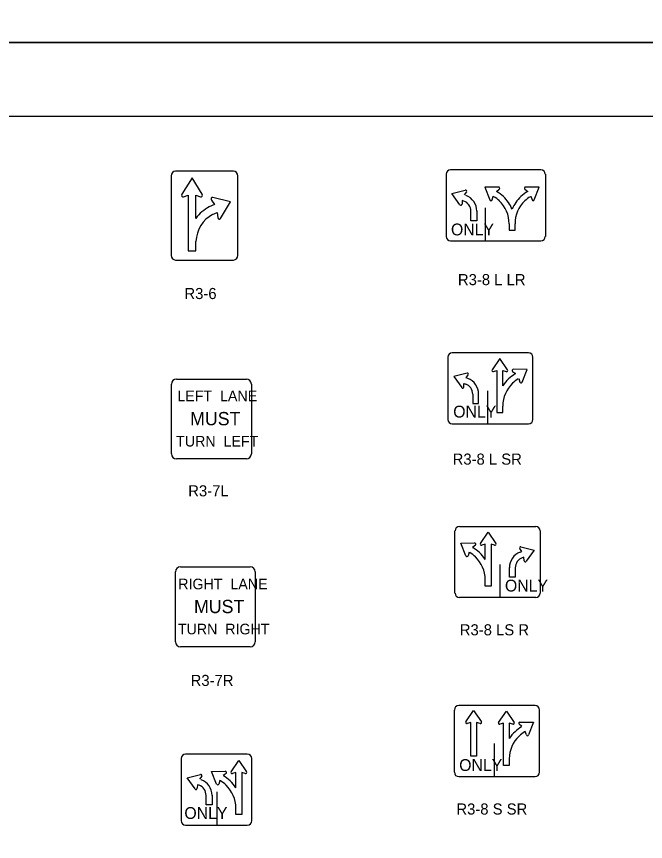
# Model space of a CAD drawing. Extents: x 42133 to 45533, y 41351 to 47951.
# Drawn here: x 42559 to 42984, y 43012 to 43569 of the extents above; entities that cross this region are included whole.
import ezdxf

# ---------------------------------------------------------------- set-up
doc = ezdxf.new("R2010")
doc.units = 0
for name, color, linetype in [('#plot_shape', 7, 'Continuous'), ('P_ODOT_PLAN_Border', 7, 'Continuous'), ('P_TRAF_SIGN_SignDetails', 7, 'Continuous')]:
    doc.layers.add(name, color=color, linetype=linetype)

msp = doc.modelspace()

# ---------------------------------------------------------------- linework, layer by layer
at = {"layer": '#plot_shape'}
for points in [[(42133.34, 43551.35), (43833.34, 43551.35), (43833.34, 44651.35), (42133.34, 44651.35)], [(42133.34, 42451.35), (43833.34, 42451.35), (43833.34, 43551.35), (42133.34, 43551.35)]]:
    msp.add_lwpolyline(points, close=True, dxfattribs=at)
at = {"layer": 'P_ODOT_PLAN_Border'}
msp.add_lwpolyline([(42208.34, 42501.35), (43808.34, 42501.35), (43808.34, 43501.35), (42208.34, 43501.35)], close=True, dxfattribs=at)
at = {"layer": 'P_TRAF_SIGN_SignDetails'}
for p, q in [((42663.19, 43461.28), (42663.19, 43407.53)), ((42699.13, 43464.4), (42666, 43464.4)), ((42705.35, 43464.4), (42699.13, 43464.4)), ((42708.17, 43454.37), (42708.17, 43461.28)), ((42849, 43462.36), (42849, 43420.39)), ((42913.14, 43465.35), (42851.99, 43465.35)), ((42916.13, 43462.36), (42916.13, 43420.39)), ((42677.27, 43460.03), (42670.44, 43448.8)), ((42684.11, 43448.8), (42677.27, 43460.03)), ((42708.17, 43407.53), (42708.17, 43454.37)), ((42853.01, 43449.36), (42861.98, 43451.63)), ((42862.8, 43450.38), (42861.28, 43448.43)), ((42884.52, 43453.73), (42875.27, 43453.68)), ((42875.27, 43453.68), (42878.64, 43445.07)), ((42883.08, 43450.77), (42885.01, 43452.34)), ((42902.26, 43452.34), (42904.2, 43450.77)), ((42912.01, 43453.68), (42902.76, 43453.73)), ((42908.64, 43445.07), (42912.01, 43453.68)), ((42671.59, 43447.09), (42674.63, 43448.16)), ((42674.63, 43448.16), (42674.63, 43410.67)), ((42679.88, 43432.46), (42679.88, 43448.17)), ((42679.88, 43448.17), (42682.95, 43447.09)), ((42690.36, 43444.77), (42692.4, 43442.03)), ((42703.28, 43443.76), (42691.36, 43446.61)), ((42858.36, 43441.81), (42853.01, 43449.36)), ((42859.92, 43444.69), (42859.79, 43442.22)), ((42861.1, 43444.25), (42859.92, 43444.69)), ((42880.12, 43445.13), (42880.85, 43447.49)), ((42880.85, 43447.49), (42881.28, 43447.2)), ((42906, 43447.2), (42906.42, 43447.49)), ((42906.42, 43447.49), (42907.15, 43445.13)), ((42692.4, 43442.03), (42688.94, 43440.36)), ((42696.49, 43432.51), (42703.28, 43443.76)), ((42875.52, 43439.76), (42875.52, 43417.48)), ((42691.13, 43435.07), (42694.37, 43436.63)), ((42694.37, 43436.63), (42694.62, 43433.07)), ((42865.8, 43431), (42865.8, 43437.48)), ((42869.79, 43437.64), (42869.79, 43431)), ((42869.79, 43431), (42865.8, 43431)), ((42891.64, 43428.93), (42891.64, 43424.53)), ((42895.63, 43424.53), (42895.63, 43428.93)), ((42891.64, 43424.53), (42895.63, 43424.53)), ((42891.64, 43424.53), (42895.63, 43424.53)), ((42679.88, 43410.67), (42679.88, 43416.98)), ((42851.99, 43417.4), (42913.14, 43417.4)), ((42674.63, 43410.67), (42679.88, 43410.67)), ((42666, 43404.42), (42705.35, 43404.42)), ((42850.21, 43338.76), (42850.21, 43296.77)), ((42904.79, 43341.76), (42853.2, 43341.76)), ((42907.78, 43296.77), (42907.78, 43338.76)), ((42885.38, 43337.96), (42880.15, 43330.32)), ((42890.62, 43330.32), (42885.38, 43337.96)), ((42863.2, 43328.02), (42854.23, 43325.76)), ((42881.03, 43329.13), (42883.39, 43329.86)), ((42883.39, 43329.86), (42883.39, 43301.38)), ((42887.38, 43319.45), (42887.38, 43329.86)), ((42887.38, 43329.86), (42889.74, 43329.13)), ((42894.01, 43329.2), (42895.94, 43327.65)), ((42903.77, 43330.55), (42894.51, 43330.61)), ((42895.94, 43327.65), (42895.61, 43327.43)), ((42900.4, 43321.93), (42903.77, 43330.55)), ((42666.79, 43324.02), (42714.02, 43324.02)), ((42854.23, 43325.76), (42859.58, 43318.21)), ((42862.5, 43324.83), (42864.02, 43326.78)), ((42863.7, 43324.39), (42862.5, 43324.83)), ((42898.18, 43324.35), (42898.91, 43321.99)), ((42663.42, 43273.42), (42663.42, 43320.65)), ((42717.39, 43320.65), (42717.39, 43273.42)), ((42861, 43318.61), (42861.14, 43321.08)), ((42861.14, 43321.08), (42862.32, 43320.64)), ((42877.22, 43293.8), (42877.22, 43316.14)), ((42867.02, 43313.87), (42867.02, 43307.39)), ((42871.01, 43307.39), (42871.01, 43314.03)), ((42867.02, 43307.39), (42871.01, 43307.39)), ((42887.38, 43301.38), (42887.38, 43305.78)), ((42883.39, 43301.38), (42887.38, 43301.38)), ((42853.2, 43293.78), (42904.79, 43293.78)), ((42714.02, 43270.05), (42666.79, 43270.05)), ((42855.05, 43179.44), (42855.05, 43221.44)), ((42858.05, 43224.43), (42909.64, 43224.43)), ((42912.63, 43221.44), (42912.63, 43179.44)), ((42872.21, 43213), (42877.45, 43220.64)), ((42877.45, 43220.64), (42882.68, 43213)), ((42859.06, 43213.22), (42868.32, 43213.28)), ((42862.44, 43204.61), (42859.06, 43213.22)), ((42868.82, 43211.88), (42866.9, 43210.32)), ((42866.9, 43210.32), (42867.22, 43210.1)), ((42875.46, 43212.53), (42873.1, 43211.8)), ((42875.46, 43202.13), (42875.46, 43212.53)), ((42881.8, 43211.8), (42879.45, 43212.53)), ((42879.45, 43212.53), (42879.45, 43184.05)), ((42899.63, 43210.7), (42908.61, 43208.44)), ((42864.66, 43207.02), (42863.93, 43204.66)), ((42900.34, 43207.5), (42898.82, 43209.46)), ((42899.13, 43207.06), (42900.34, 43207.5)), ((42908.61, 43208.44), (42903.26, 43200.88)), ((42901.7, 43203.75), (42900.52, 43203.32)), ((42901.84, 43201.29), (42901.7, 43203.75)), ((42666.04, 43146.53), (42666.04, 43193.75)), ((42669.4, 43197.13), (42716.63, 43197.13)), ((42720, 43193.75), (42720, 43146.53)), ((42885.62, 43176.47), (42885.62, 43198.81)), ((42891.83, 43190.06), (42891.83, 43196.71)), ((42895.82, 43196.55), (42895.82, 43190.06)), ((42875.46, 43184.05), (42875.46, 43188.45)), ((42895.82, 43190.06), (42891.83, 43190.06)), ((42879.45, 43184.05), (42875.46, 43184.05)), ((42909.64, 43176.45), (42858.05, 43176.45)), ((42716.63, 43143.16), (42669.4, 43143.16)), ((42854.6, 43100.4), (42854.6, 43058.41)), ((42909.19, 43103.39), (42857.59, 43103.39)), ((42862.41, 43092.49), (42867.65, 43100.12)), ((42867.65, 43100.12), (42872.88, 43092.49)), ((42884.55, 43091.96), (42889.78, 43099.59)), ((42889.78, 43099.59), (42895.02, 43091.96)), ((42912.18, 43058.41), (42912.18, 43100.4)), ((42865.65, 43092.03), (42863.29, 43091.29)), ((42865.65, 43069.31), (42865.65, 43092.03)), ((42872, 43091.29), (42869.64, 43092.03)), ((42869.64, 43092.03), (42869.64, 43069.31)), ((42887.79, 43091.49), (42885.43, 43090.77)), ((42887.79, 43063.01), (42887.79, 43091.49)), ((42894.14, 43090.77), (42891.78, 43091.49)), ((42891.78, 43091.49), (42891.78, 43081.09)), ((42900.33, 43089.29), (42898.41, 43090.84)), ((42898.91, 43092.23), (42908.17, 43092.19)), ((42908.17, 43092.19), (42904.79, 43083.57)), ((42902.57, 43085.99), (42902.15, 43085.69)), ((42903.3, 43083.63), (42902.57, 43085.99)), ((42881.57, 43077.79), (42881.57, 43055.5)), ((42669.98, 43067.67), (42669.98, 43025.67)), ((42714.58, 43070.66), (42672.98, 43070.66)), ((42703.65, 43058.76), (42708.89, 43066.4)), ((42708.89, 43066.4), (42714.12, 43058.76)), ((42717.64, 43025.67), (42717.64, 43067.67)), ((42869.64, 43069.31), (42865.65, 43069.31)), ((42891.78, 43067.42), (42891.78, 43063.01)), ((42891.78, 43063.01), (42887.79, 43063.01)), ((42674, 43054.66), (42682.97, 43056.93)), ((42679.35, 43047.11), (42674, 43054.66)), ((42683.79, 43055.69), (42682.28, 43053.73)), ((42690.5, 43058.99), (42699.76, 43059.04)), ((42693.88, 43050.37), (42690.5, 43058.99)), ((42700.26, 43057.64), (42698.34, 43056.09)), ((42706.89, 43058.3), (42704.54, 43057.57)), ((42706.89, 43047.89), (42706.89, 43058.3)), ((42713.25, 43057.57), (42710.89, 43058.3)), ((42710.89, 43058.3), (42710.89, 43029.81)), ((42857.59, 43055.41), (42909.19, 43055.41)), ((42680.91, 43049.99), (42680.78, 43047.52)), ((42682.09, 43049.55), (42680.91, 43049.99)), ((42696.1, 43052.79), (42695.36, 43050.43)), ((42696.52, 43052.49), (42696.1, 43052.79)), ((42694.09, 43045.06), (42694.09, 43022.77)), ((42686.79, 43036.29), (42686.79, 43042.78)), ((42690.78, 43042.94), (42690.78, 43036.29)), ((42690.78, 43036.29), (42686.79, 43036.29)), ((42706.89, 43029.81), (42706.89, 43034.22)), ((42710.89, 43029.81), (42706.89, 43029.81)), ((42672.98, 43022.68), (42714.65, 43022.68))]:
    msp.add_line(p, q, dxfattribs=at)
for centre, radius, start, end in [((42851.99, 43462.36), 2.99, 90, 180), ((42913.13, 43462.36), 2.99, 360, 90), ((42862.18, 43450.87), 0.785, 321.8979, 104.4235), ((42870.48, 43428.98), 25.16, 46.5584, 59.9731), ((42884.51, 43452.95), 0.788, 309.1769, 90.0726), ((42916.79, 43428.98), 25.16, 120.0268, 133.4416), ((42902.76, 43452.95), 0.788, 89.9274, 230.8231), ((42858.59, 43437.49), 11.2, 359.9553, 69.6508), ((42879.37, 43445.35), 0.784, 201.0468, 343.2731), ((42870.48, 43428.98), 21.17, 46.5584, 59.3388), ((42870.47, 43428.99), 21.17, 359.8578, 46.5584), ((42870.47, 43428.99), 25.16, 22.989, 46.5571), ((42916.8, 43428.99), 25.16, 133.4727, 157.011), ((42916.8, 43428.99), 21.17, 133.4416, 180.1422), ((42916.79, 43428.98), 21.17, 120.6612, 133.4416), ((42907.9, 43445.35), 0.784, 196.7269, 338.9532), ((42859, 43442.26), 0.784, 214.8159, 357.2951), ((42858.59, 43437.49), 7.21, 359.9553, 69.6508), ((42851.99, 43420.39), 2.99, 180, 270), ((42913.13, 43420.39), 2.99, 270, 0), ((42853.2, 43338.77), 2.99, 90, 180), ((42904.79, 43338.77), 2.99, 0, 90), ((42863.4, 43327.27), 0.786, 321.8979, 104.4235), ((42880.81, 43329.89), 0.793, 146.7732, 285.9799), ((42889.98, 43329.88), 0.785, 252.4081, 34.8389), ((42908.56, 43305.83), 25.18, 120.6612, 133.4416), ((42894.52, 43329.81), 0.788, 89.9274, 230.8231), ((42666.79, 43320.65), 3.37, 90, 180), ((42714.02, 43320.65), 3.37, 0, 90), ((42859.81, 43313.88), 11.21, 359.9553, 69.6508), ((42908.57, 43305.84), 25.18, 133.4429, 147.2748), ((42908.56, 43305.83), 21.19, 120.6612, 133.4416), ((42899.66, 43322.21), 0.785, 196.7269, 338.9532), ((42860.22, 43318.65), 0.785, 214.8159, 357.2951), ((42859.81, 43313.88), 7.22, 359.9553, 69.6508), ((42908.57, 43305.84), 21.19, 133.4416, 180.1422), ((42853.2, 43296.77), 2.99, 180, 270), ((42904.79, 43296.77), 2.99, 270, 0), ((42666.79, 43273.42), 3.37, 180, 270), ((42714.02, 43273.42), 3.37, 270, 0), ((42858.05, 43221.44), 2.99, 90, 180), ((42909.64, 43221.44), 2.99, 0, 90), ((42868.32, 43212.49), 0.788, 309.1769, 90.0726), ((42872.86, 43212.55), 0.785, 145.1612, 287.5919), ((42882.02, 43212.56), 0.793, 254.0201, 33.2268), ((42899.44, 43209.94), 0.786, 75.5765, 218.1021), ((42863.17, 43204.89), 0.785, 201.0468, 343.2731), ((42854.28, 43188.51), 21.19, 46.5584, 59.3388), ((42854.28, 43188.51), 25.18, 46.5584, 59.3388), ((42854.27, 43188.51), 25.18, 32.7252, 46.5571), ((42903.03, 43196.55), 11.21, 110.3492, 180.0447), ((42854.27, 43188.51), 21.19, 359.8578, 46.5584), ((42903.03, 43196.55), 7.22, 110.3492, 180.0447), ((42902.62, 43201.32), 0.785, 182.7049, 325.1841), ((42669.41, 43193.75), 3.37, 90, 180), ((42716.63, 43193.75), 3.37, 0, 90), ((42858.05, 43179.44), 2.99, 180, 270), ((42909.64, 43179.44), 2.99, 270, 0), ((42669.41, 43146.52), 3.37, 180, 270), ((42716.63, 43146.52), 3.37, 270, 0), ((42857.6, 43100.4), 2.99, 90, 180), ((42909.18, 43100.4), 2.99, 0, 90), ((42863.07, 43092.06), 0.793, 146.7732, 285.9799), ((42872.24, 43092.04), 0.785, 252.4081, 34.8389), ((42885.21, 43091.52), 0.793, 146.7732, 285.9799), ((42894.37, 43091.51), 0.785, 252.4081, 34.8389), ((42912.95, 43067.47), 25.18, 120.6612, 133.4416), ((42898.91, 43091.45), 0.788, 89.9274, 230.8231), ((42912.96, 43067.48), 21.19, 133.4416, 180.1422), ((42912.96, 43067.48), 25.18, 133.4429, 147.2748), ((42912.95, 43067.47), 21.19, 120.6612, 133.4416), ((42904.06, 43083.85), 0.785, 196.7269, 338.9532), ((42672.97, 43067.67), 2.99, 90, 180), ((42714.65, 43067.67), 2.99, 0, 90), ((42683.17, 43056.17), 0.786, 321.8979, 104.4235), ((42685.72, 43034.27), 25.18, 46.5584, 59.3388), ((42699.76, 43058.25), 0.788, 309.1769, 90.0726), ((42704.3, 43058.32), 0.785, 145.1612, 287.5919), ((42713.46, 43058.33), 0.793, 254.0201, 33.2268), ((42857.6, 43058.41), 2.99, 180, 270), ((42909.18, 43058.41), 2.99, 270, 0), ((42679.58, 43042.79), 7.22, 359.9553, 69.6508), ((42679.58, 43042.79), 11.21, 359.9553, 69.6508), ((42694.61, 43050.65), 0.785, 201.0468, 343.2731), ((42685.72, 43034.27), 21.19, 46.5584, 59.3388), ((42685.71, 43034.28), 21.19, 359.8578, 46.5584), ((42685.71, 43034.28), 25.18, 32.7252, 46.5571), ((42679.99, 43047.56), 0.785, 214.8159, 357.2951), ((42672.97, 43025.68), 2.99, 180, 270), ((42714.65, 43025.68), 2.99, 270, 0)]:
    msp.add_arc(centre, radius, start, end, dxfattribs=at)
for centre, major_axis, start_param, end_param in [((42665.99, 43461.28), (0, 3.12), 0, 1.570796), ((42705.35, 43461.28), (0, 3.12), 4.712389, 6.283185), ((42671.26, 43448.15), (0, 1.13), 0.952295, 3.471349), ((42683.26, 43448.16), (0, 1.14), 2.834975, 5.307752), ((42691.13, 43445.51), (0, 1.13), 6.048656, 8.56771), ((42698.96, 43415.67), (0, -27.05), 3.565963, 4.041832), ((42698.96, 43415.67), (0, -21.25), 3.561091, 4.65619), ((42695.63, 43433.15), (0, -1.14), 4.789743, 7.262521), ((42665.99, 43407.54), (0, -3.12), 4.712389, 6.283185), ((42705.35, 43407.54), (0, -3.12), 0, 1.570796)]:
    msp.add_ellipse(centre, major_axis=major_axis, ratio=0.8997, start_param=start_param, end_param=end_param, dxfattribs=at)

# ---------------------------------------------------------------- texts
for s, height, p in [('ONLY', 7.996, (42852.34, 43421.06)), ('R3-8 L LR', 7.5, (42857.04, 43387.43)), ('R3-6', 7.5, (42672.13, 43378.04)), ('LEFT  LANE', 7.188, (42667.35, 43309.03)), ('ONLY', 7.996, (42853.85, 43298)), ('MUST', 8.98, (42675.98, 43292.77)), ('TURN  LEFT', 7.188, (42666.52, 43278.43)), ('R3-8 L SR', 7.5, (42853.45, 43266.18)), ('R3-7L', 7.5, (42674.71, 43244.75)), ('RIGHT  LANE', 7.1877, (42667.97, 43181.97)), ('ONLY', 7.996, (42888.82, 43180.47)), ('MUST', 8.979, (42678.6, 43165.87)), ('TURN  RIGHT', 7.1877, (42667.71, 43151.53)), ('R3-8 LS R', 7.5, (42858.29, 43150.86)), ('R3-7R', 7.5, (42676.32, 43116.67)), ('ONLY', 7.996, (42857.88, 43059.24)), ('R3-8 S SR', 7.5, (42855.99, 43029.8)), ('ONLY', 7.996, (42672.1, 43026.84))]:
    msp.add_text(s, height=height, dxfattribs=at).set_placement(p)

doc.saveas('drawing.dxf')
